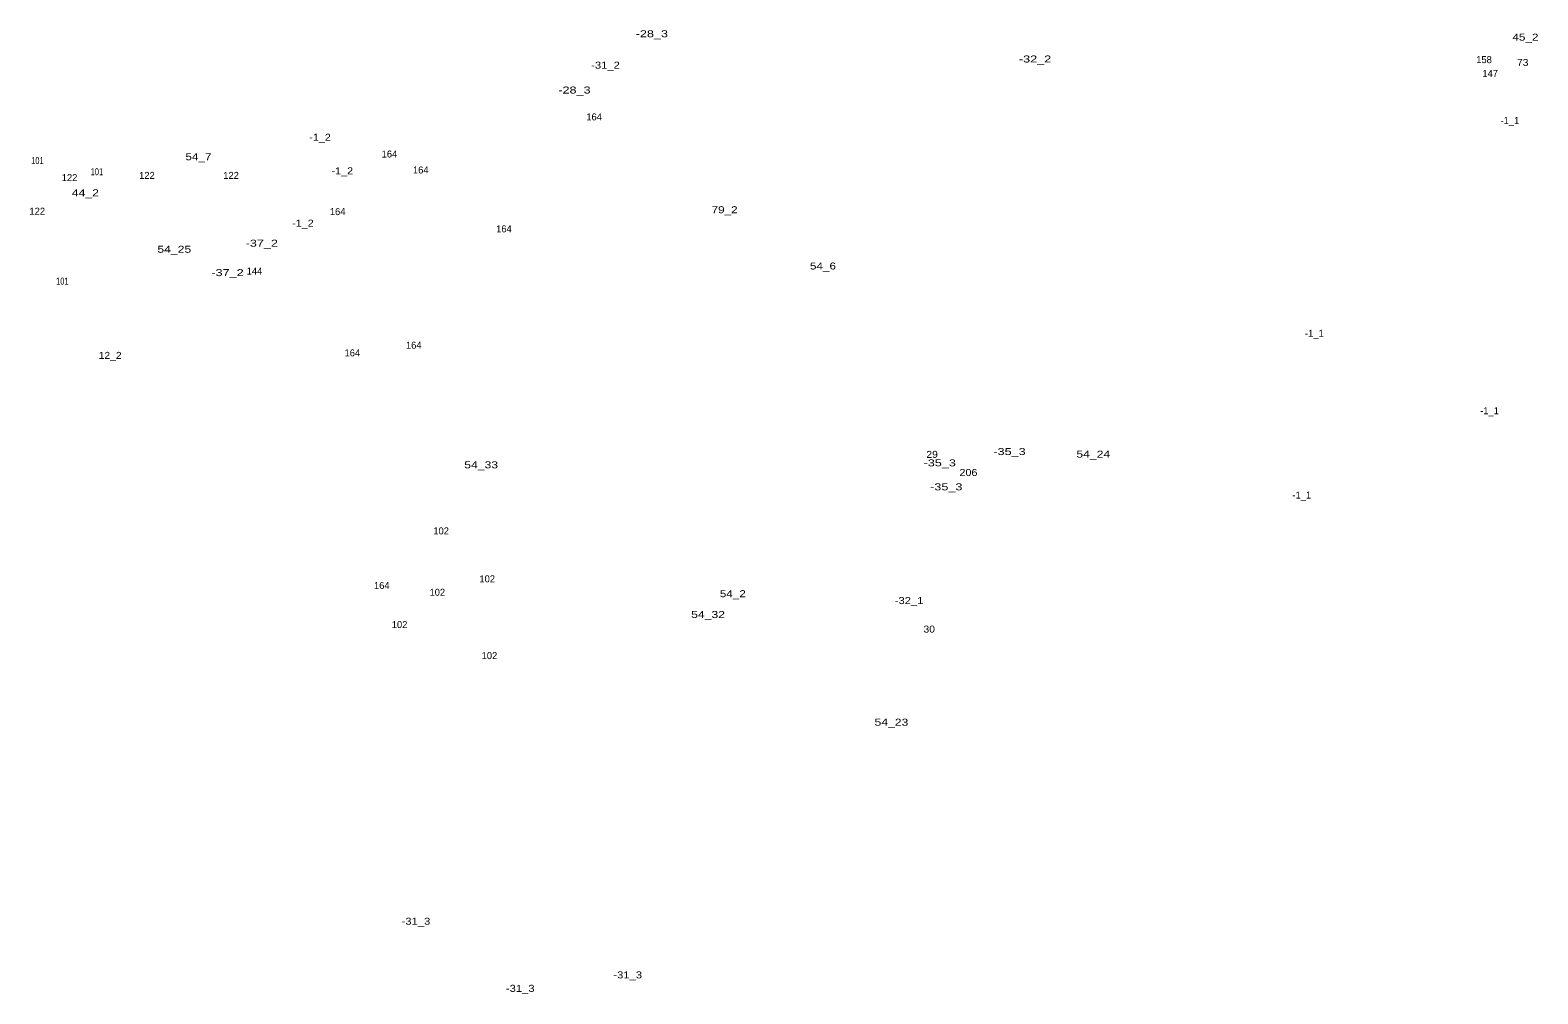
# Model space of a CAD drawing. Extents: x -660405 to -657848, y -988475 to -986360.
# Drawn here: x -658950 to -658088, y -988475 to -987924 of the extents above; entities that cross this region are included whole.
import ezdxf
from ezdxf.enums import TextEntityAlignment as Align

# ---------------------------------------------------------------- set-up
doc = ezdxf.new("R2010")
doc.units = 0
doc.header["$LTSCALE"] = 1.6
doc.layers.add('24', color=7, linetype='Continuous')

msp = doc.modelspace()

# ---------------------------------------------------------------- texts
at = {"layer": '24'}
for s, width, p in [('-28_3', 1.35, (-658594.429, -987927.68)), ('45_2', 1.25, (-658095.12, -987929.63)), ('-32_2', 1.35, (-658375.39, -987942.12)), ('-31_2', 1.2, (-658620.91, -987945.62)), ('73', 1.1, (-658096.65, -987944.09)), ('-28_3', 1.35, (-658638.66, -987959.86)), ('-1_2', 1.15, (-658784.079, -987986.86)), ('101', 0.8, (-658945.62, -988000.19)), ('54_7', 1.25, (-658853.58, -987997.99)), ('101', 0.8, (-658911.62, -988006.59)), ('-1_2', 1.15, (-658771.35, -988006.06)), ('44_2', 1.3, (-658918.201, -988018.64)), ('79_2', 1.25, (-658552.84, -988028.3)), ('-1_2', 1.15, (-658793.86, -988035.96)), ('54_25', 1.3, (-658867.38, -988050.92)), ('-37_2', 1.35, (-658817.38, -988047.44)), ('54_6', 1.25, (-658496.63, -988060.49)), ('101', 0.8, (-658931.36, -988069.12)), ('-37_2', 1.35, (-658836.94, -988064.27)), ('12_2', 1.1, (-658904.05, -988111.6)), ('54_33', 1.3, (-658691.971, -988174.17)), ('-35_3', 1.35, (-658429.89, -988173.05)), ('29', 1.1, (-658434.24, -988168.19)), ('-35_3', 1.35, (-658389.99, -988166.6)), ('54_24', 1.3, (-658342.111, -988168.08)), ('206', 1.15, (-658413.471, -988178.55)), ('-35_3', 1.35, (-658426.14, -988186.76)), ('54_2', 1.25, (-658548.15, -988247.86)), ('-32_1', 1.2, (-658447.4, -988251.8)), ('54_32', 1.3, (-658562.291, -988259.77)), ('30', 1.1, (-658435.89, -988268.11)), ('54_23', 1.3, (-658457.49, -988321.36)), ('-31_3', 1.2, (-658729.25, -988435.12)), ('-31_3', 1.2, (-658608.23, -988465.84)), ('-31_3', 1.2, (-658669.65, -988473.52))]:
    msp.add_text(s, height=4, dxfattribs=dict(at, width=width)).set_placement(p, align=Align.CENTER)
for s, p in [('158', (-658118.79, -987942.48)), ('147', (-658115.26, -987950.38)), ('164', (-658627.41, -987975.24)), ('-1_1', (-658104, -987977.27)), ('164', (-658744.4, -987996.45)), ('122', (-658927.25, -988009.95)), ('122', (-658883.01, -988008.67)), ('122', (-658834.929, -988008.67)), ('164', (-658726.49, -988005.59)), ('122', (-658945.709, -988029.15)), ('164', (-658774.01, -988029.37)), ('164', (-658678.96, -988039.24)), ('144', (-658821.53, -988063.39)), ('164', (-658730.51, -988105.77)), ('-1_1', (-658215.76, -988098.98)), ('164', (-658765.61, -988110.16)), ('-1_1', (-658115.62, -988143.23)), ('-1_1', (-658222.949, -988191.43)), ('102', (-658714.86, -988211.95)), ('164', (-658748.79, -988243.18)), ('102', (-658688.53, -988239.37)), ('102', (-658717.05, -988247.05)), ('102', (-658738.62, -988265.52)), ('102', (-658687.25, -988283.26))]:
    msp.add_text(s, height=4, dxfattribs=at).set_placement(p, align=Align.CENTER)

doc.saveas('drawing.dxf')
